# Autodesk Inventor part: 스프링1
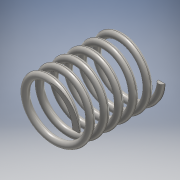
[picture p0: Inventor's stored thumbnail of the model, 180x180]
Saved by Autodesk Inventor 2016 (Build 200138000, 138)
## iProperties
Created: 2019-07
Part Number: 스프링1
Material: 강철, 탄소
Document SubType Name: Modeling
Designer: 602-01
Density: 7.85 g/cm^3
Appearance: 반연마
Mass: 7.77017 g
Surface Area: 20.0872 cm^2
Volume: 0.989831 cm^3
Author: 602-01
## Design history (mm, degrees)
sketch "스케치1"
  geometry: L1 (0, 0)-(8.5, 0); L2 (8.5, 0)-(8.5, 25.33); L3 (8.5, 25.33)-(0, 25.33); L4 (0, 25.33)-(0, 0); C1 r 1 at (8.5, 0)
  constraints: 8 end point, 2 parallel, 1 centre point, 1 coincident, 1 horizontal, 1 perpendicular
  dimensions: "d0" = 17 diameter of L2 L4; "d1" = 25.33013 distance between parallel lines of L1 L3 (derived); "d2" = 2 diameter of C1
feature "코일1" sketch "스케치1" pitch "d3" = 10; turns "d5" = 6; dims "d4" = 25.33013 (= d1), "d6" = 0, angle "d7" = 90 deg, angle "d8" = 90 deg, "d9" = 0, "d10" = 0
sketch "스케치2"
  geometry: L1 (-7.5, 0)-(-9.5, 0) reference; 1 further point
  constraints: 1 horizontal alignment
extrude "돌출1" cut sketch "스케치2" distance "d11" = 10; taper "d12" = 0 deg
node "작업 평면1"
sketch "스케치3"
  geometry: L1 (-1, 0)-(1, 0) reference; 1 further point
  constraints: 1 horizontal alignment
extrude "돌출2" cut sketch "스케치3" distance "d14" = 10; taper "d15" = 0 deg
node "솔리드1"
node "절단 모서리 투영1"
node "절단 모서리 투영2"
other parameters: "d13" = 90 deg
